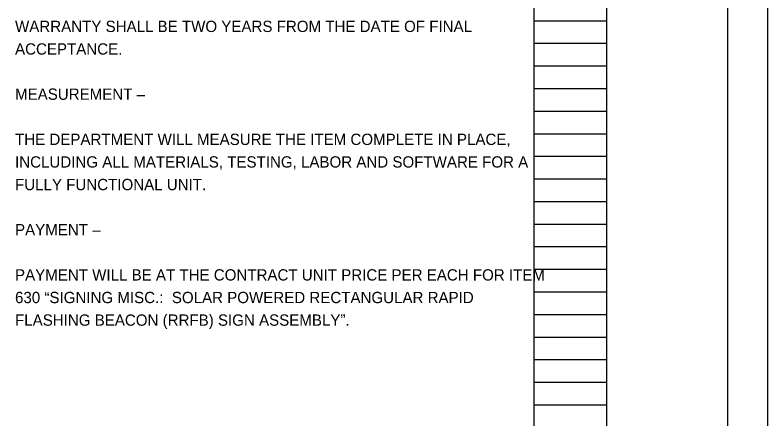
# Model space of a CAD drawing. Extents: x 0 to 34, y 0 to 22.
# Drawn here: x 24.66 to 34, y 5.01 to 10.01 of the extents above; entities that cross this region are included whole.
import ezdxf

# ---------------------------------------------------------------- set-up
doc = ezdxf.new("R2010")
doc.units = 0
for name, color, linetype in [('SH_Border', 7, 'Continuous'), ('SH_Cut_Line', 7, 'Continuous'), ('SH_Data', 7, 'Continuous'), ('SH_Text', 7, 'Continuous')]:
    doc.layers.add(name, color=color, linetype=linetype)

msp = doc.modelspace()

# ---------------------------------------------------------------- linework, layer by layer
at = {"layer": 'SH_Border'}
msp.add_line((32, 0.5), (32, 21.5), dxfattribs=at)
msp.add_lwpolyline([(1.5, 21.5), (33.5, 21.5), (33.5, 0.5), (1.5, 0.5)], close=True, dxfattribs=at)
at = {"layer": 'SH_Cut_Line'}
msp.add_lwpolyline([(0, 0), (34, 0), (34, 22), (0, 22)], close=True, dxfattribs=at)
at = {"layer": 'SH_Data'}
for p, q in [((31.1, 0.98), (31.1, 21.14)), ((32, 0.98), (32, 21.14)), ((31.1, 9.94), (32, 9.94)), ((31.1, 9.66), (32, 9.66)), ((31.1, 9.38), (32, 9.38)), ((31.1, 9.1), (32, 9.1)), ((31.1, 8.82), (32, 8.82)), ((31.1, 8.54), (32, 8.54)), ((31.1, 8.26), (32, 8.26)), ((31.1, 7.98), (32, 7.98)), ((31.1, 7.7), (32, 7.7)), ((31.1, 7.42), (32, 7.42)), ((31.1, 7.14), (32, 7.14)), ((31.1, 6.86), (32, 6.86)), ((31.1, 6.58), (32, 6.58)), ((31.1, 6.3), (32, 6.3)), ((31.1, 6.02), (32, 6.02)), ((31.1, 5.74), (32, 5.74)), ((31.1, 5.46), (32, 5.46)), ((31.1, 5.18), (32, 5.18))]:
    msp.add_line(p, q, dxfattribs=at)

# ---------------------------------------------------------------- texts
at = {"layer": 'SH_Text'}
for s, p in [('WARRANTY SHALL BE TWO YEARS FROM THE DATE OF FINAL ', (24.66, 9.8)), ('ACCEPTANCE.', (24.66, 9.52)), ('MEASUREMENT – ', (24.66, 8.96)), ('THE DEPARTMENT WILL MEASURE THE ITEM COMPLETE IN PLACE, ', (24.66, 8.4)), ('INCLUDING ALL MATERIALS, TESTING, LABOR AND SOFTWARE FOR A ', (24.66, 8.12)), ('FULLY FUNCTIONAL UNIT.', (24.66, 7.84)), ('PAYMENT – ', (24.66, 7.28)), ('PAYMENT WILL BE AT THE CONTRACT UNIT PRICE PER EACH FOR ITEM ', (24.66, 6.72)), ('630 “SIGNING MISC.:  SOLAR POWERED RECTANGULAR RAPID ', (24.66, 6.44)), ('FLASHING BEACON (RRFB) SIGN ASSEMBLY”.', (24.66, 6.16))]:
    msp.add_text(s, height=0.14, dxfattribs=at).set_placement(p)

doc.saveas('drawing.dxf')
